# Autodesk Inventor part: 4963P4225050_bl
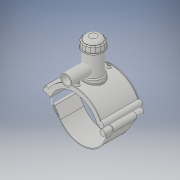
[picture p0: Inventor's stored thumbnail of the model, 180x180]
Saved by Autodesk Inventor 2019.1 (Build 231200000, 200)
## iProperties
Created: 2017-07
Part Number: 4963P4225050_bl
Material: Generic
Document SubType Name: Modeling
Designer: KIM
Density: 1 g/cm^3
Appearance: Default
Author: KIM
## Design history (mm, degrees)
derived "4963P4.ipt"
feature "Solid1::4963P4.ipt" dims "ScaleForDerivedMember" = 10
feature "Solid2::4963P4.ipt" dims "ScaleForDerivedMember" = 10
feature "Solid3::4963P4.ipt" dims "ScaleForDerivedMember" = 10
tag "TaggingFeature1"
body "Solid1"
body "Solid2"
body "Solid3"
other parameters: "d0" = 225 [user parameter], "d2" = 295.1 [user parameter], "d3" = 56.25 [user parameter], "d4" = 176 [user parameter], "d5" = 0 [user parameter], "d6" = 0.1 [user parameter], "d8" = 0 [user parameter], "d19" = 6 [user parameter], "d20" = 6 [user parameter], "d21" = 105.6 [user parameter], "d23" = 0 [user parameter], "d24" = 52.8 [user parameter], "d26" = 0 [user parameter], "d27" = 3 [user parameter], "d28" = 3 [user parameter], "d29" = 3 [user parameter], "d30" = 75 [user parameter], "d31" = 6 [user parameter], "d32" = 0 [user parameter], "d33" = 0 [user parameter], "d34" = 0.6 [user parameter], "d40" = 135.72 [user parameter], "d43" = 0 [user parameter], "d45" = 0 [user parameter], "d47" = 236.1 [user parameter], "d70" = 15 [user parameter], "d72" = 0 [user parameter], "d73" = 6 [user parameter], "d75" = 5 [user parameter], "d76" = 0 [user parameter], "d77" = 11.25 [user parameter], "d78" = 142.5 [user parameter], "d79" = 15 [user parameter], "d80" = 70.4 [user parameter], "d82" = 5 deg [user parameter], "d84" = 4 [user parameter], "d85" = 14 [user parameter], "d86" = 0 [user parameter], "d87" = 3 [user parameter], "d88" = 0 [user parameter], "d89" = 1 [user parameter], "d90" = 1 [user parameter], "d91" = 140.8 [user parameter], "d92" = 0 [user parameter], "d93" = 0.5 [user parameter], "d94" = 118.42105 [user parameter], "d96" = 266.22 [user parameter], "d97" = 3.52 [user parameter], "d98" = 0 [user parameter], "d102" = 2.25 [user parameter], "d120" = 140 deg [user parameter], "d121" = 24.228 [user parameter], "d122" = 20 deg [user parameter], "d123" = 522 [user parameter], "d124" = 156.6 [user parameter], "d126" = 0 [user parameter], "d143" = 231.75 [user parameter], "d145" = 27.69231 [user parameter], "d149" = 3.375 [user parameter], "d150" = 30.46154 [user parameter], "d153" = 176 [user parameter], "d154" = 0 [user parameter], "d156" = 130.5 [user parameter], "d157" = 160 deg [user parameter], "d159" = 7.2 [user parameter], "d161" = 3.375 [user parameter], "d162" = 105.6 [user parameter], "d163" = 0 [user parameter], "d164" = 112.5 [user parameter], "d167" = 22.5 [user parameter], "d168" = 127.31707 [user parameter], "d170" = 3.375 [user parameter], "d172" = 0 [user parameter], "d173" = 1 [user parameter], "d175" = 112.5 [user parameter], "d176" = 20 deg [user parameter], "d177" = 15.75 [user parameter], "d178" = 36 [user parameter], "d180" = 0 [user parameter], "d183" = 14.4 [user parameter], "d184" = 12.6 [user parameter], "d185" = 57.2 [user parameter], "d186" = 57.2 [user parameter], "d187" = 130.5 [user parameter], "d188" = 10.8 [user parameter], "d189" = 15.75 [user parameter], "d190" = 0 [user parameter], "d191" = 195.75 [user parameter], "d193" = 7.2 [user parameter], "d194" = 6.16 [user parameter], "d195" = 90 deg [user parameter], "d197" = 0 [user parameter], "d199" = 0 [user parameter], "d200" = 18 [user parameter], "d202" = 0 [user parameter], "d203" = 177 [user parameter], "d204" = 85.5 [user parameter], "d205" = 63 [user parameter], "d206" = 76.5 [user parameter], "d207" = 132.75 [user parameter], "d208" = 138.06 [user parameter], "d209" = 164.61 [user parameter], "d210" = 77.4 [user parameter], "d212" = 72 [user parameter], "d213" = 35.1 [user parameter], "d216" = 0 [user parameter], "d217" = 22.5 [user parameter], "d218" = 22.5 [user parameter], "d219" = 4.5 [user parameter], "d222" = 225 [user parameter], "d224" = 0 [user parameter], "d225" = 64 [user parameter], "d228" = 123 [user parameter], "d230" = 4.5 [user parameter], "d_" = 225 [user parameter], "B_" = 227 [user parameter], "L_" = 176 [user parameter], "d_t" = 6 [user parameter], "H_2" = 177 [user parameter], "H_1" = 64 [user parameter]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
